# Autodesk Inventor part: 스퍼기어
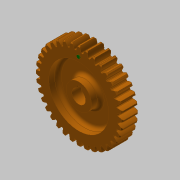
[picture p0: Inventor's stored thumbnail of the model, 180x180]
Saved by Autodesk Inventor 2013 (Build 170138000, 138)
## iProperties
Created: 2019-01
Part Number: 스퍼기어
Material: 알루미늄 6061
Document SubType Name: Modeling
Designer: mduedu
Density: 2.71 g/cm^3
Mass: 116.095 g
Surface Area: 165.902 cm^2
Volume: 42.8394 cm^3
Author: mduedu
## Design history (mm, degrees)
sketch "스케치1"
  geometry: C1 r 33.5 at (0, 0); C2 r 36 at (0, 0); C3 r 38 at (0, 0); 1 further point
  constraints: 3 centre point, 3 coincident
  dimensions: "d0" = 67 diameter of C1; "d2" = 72 diameter of C2; "d3" = 76 diameter of C3
extrude "돌출1" new body sketch "스케치1" distance "d4" = 14; taper "d5" = 0 deg
sketch "스케치2"
  geometry: L1 (0, 0)-(-38, 0); L2 (0, 0)-(0, 38); L3 (-0.57, 0)-(-0.57, 37.996); L4 (-1.57, 0)-(-1.57, 35.966); L5 (-2.07, 0)-(-2.07, 33.436); A1 r 38 centre (0, 0) between (-38, 0) and (0, 38) reference; A2 r 9.246 centre (7.162, 32.926) between (-0.57, 37.996) and (-2.07, 33.436); A3 r 9.246 centre (-7.162, 32.926) between (2.07, 33.436) and (0.57, 37.996); A4 r 33.5 centre (0, 0) between (2.07, 33.436) and (-2.07, 33.436); A5 r 38 centre (0, 0) between (0.57, 37.996) and (-0.57, 37.996); 2 further points
  constraints: 12 point on circle, 10 end point, 4 centre point, 3 parallel, 3 symmetric about line, 2 coincident, 1 horizontal, 1 perpendicular, 5 other
  dimensions: "d6" = 0.5 distance between parallel lines of L4 L5; "d8" = 1 distance between parallel lines of L3 L4; "d9" = 1.57 distance between parallel lines of L2 L4
extrude "돌출2" join sketch "스케치2" stored distance "d10" = 14; taper "d11" = 0 deg
chamfer "모따기1" distance "d12" = 1; stored, may be unused: second distance "d13" = 2, angle "d14" = 45 deg
fillet "모깎기1" dims "d15" = 0.5
sketch "스케치3"
  geometry: C1 r 11 at (0, 0); 1 further point
  constraints: 1 centre point, 1 coincident
  dimensions: "d19" = 22 diameter of C1
extrude "돌출3" join sketch "스케치3" distance "d20" = 6; taper "d21" = 0 deg
fillet "모깎기2" dims "d22" = 3
sketch "스케치4"
  geometry: C1 r 11 at (0, 0); C2 r 26 at (0, 0); 1 further point
  constraints: 2 centre point, 2 coincident
  dimensions: "d23" = 22 diameter of C1; "d24" = 52 diameter of C2
extrude "돌출4" cut sketch "스케치4" distance "d25" = 8; taper "d26" = 0 deg
fillet "모깎기3" dims "d27" = 3
sketch "스케치5" dims "d28" = 60
  geometry: C1 r 1.5 at (0, 30); 2 further points
  constraints: 2 vertical alignment, 1 centre point, 1 coincident, 2 other
  dimensions: "d29" = 3 diameter of C1
extrude "돌출5" join sketch "스케치5" distance "d30" = 0.5; taper "d31" = 0 deg
sketch "스케치6"
  geometry: L1 (-2, 5.657)-(2, 5.657); L2 (2, 5.657)-(2, 7.8); L3 (2, 7.8)-(-2, 7.8); L4 (-2, 7.8)-(-2, 5.657); A1 r 6 centre (0, 0) between (-2, 5.657) and (2, 5.657); 1 further point
  constraints: 8 end point, 2 parallel, 2 point on circle, 1 centre point, 1 coincident, 1 horizontal, 1 perpendicular
  dimensions: "d32" = 13.8 dimension on A1 L3; "d34" = 4 distance of L2.end L3.end; "d35" = 12 diameter of A1
extrude "돌출6" cut sketch "스케치6" stored distance "d36" = 0.5; taper "d37" = 0 deg
chamfer "모따기2" distance "d38" = 1; stored, may be unused: second distance "d39" = 2, angle "d40" = 45 deg
node "솔리드1"
pattern_circular "원형 패턴1" dims "d17" = 360 deg
